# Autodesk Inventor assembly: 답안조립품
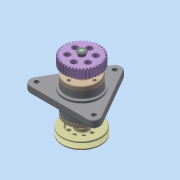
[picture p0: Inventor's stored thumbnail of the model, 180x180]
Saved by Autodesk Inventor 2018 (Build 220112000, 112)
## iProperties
Created: 2023-04
Part Number: 답안조립품
Material: 일반
Document SubType Name: Assembly
Designer: 강의실04
Author: 강의실04
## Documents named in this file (11)
- C:\Users\kimgi\Desktop\730407V1005\730407V1005\답안조립품.iam
- C:\Users\kimgi\Desktop\730407V1005\730407V1005\본체.ipt
- C:\Users\kimgi\Desktop\730407V1005\베어링 6204.ipt
- C:\Users\kimgi\Desktop\730407V1005\축.ipt
- C:\Users\kimgi\Desktop\730407V1005\커버.ipt
- C:\Users\kimgi\Desktop\730407V1005\오일 실 20 32 8.ipt
- C:\Users\kimgi\Desktop\730407V1005\묻힘키 5x5x16.ipt
- C:\Users\kimgi\Desktop\730407V1005\볼트 M4 x 12.ipt
- C:\Users\kimgi\Desktop\730407V1005\v-벨트풀리.ipt
- C:\Users\kimgi\Desktop\730407V1005\스퍼기어.ipt
- C:\Users\kimgi\Desktop\730407V1005\6각 플랜지 너트 M10.ipt
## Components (3 placed, 2 different names)
1. v-벨트풀리:1
2. 6각 플랜지 너트 M10:1
3. 6각 플랜지 너트 M10:2
